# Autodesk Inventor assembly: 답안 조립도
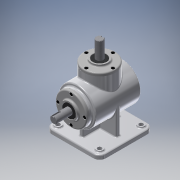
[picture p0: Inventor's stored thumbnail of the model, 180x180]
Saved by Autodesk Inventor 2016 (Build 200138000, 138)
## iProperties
Created: 2015-07
Part Number: 답안 조립도
Document SubType Name: Assembly
Designer: Administrator
Author: Administrator
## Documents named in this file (14)
- C:\Users\Administrator\Desktop\450706V1007\답안 조립도.iam
- C:\Users\Administrator\Desktop\450706V1007\본체.ipt
- C:\Users\Administrator\Desktop\450706V1007\커버.ipt
- C:\Users\Administrator\Desktop\450706V1007\메인 축.ipt
- 메인 축.ipt
- C:\Users\Administrator\Desktop\450706V1007\키 5x5.ipt
- C:\Users\Administrator\Desktop\450706V1007\메인 베벨기어.ipt
- C:\Users\Administrator\Desktop\450706V1007\베어링 6203.ipt
- C:\Users\Administrator\Desktop\450706V1007\서브 축.ipt
- 서브 축.ipt
- C:\Users\Administrator\Desktop\450706V1007\키 4x4.ipt
- C:\Users\Administrator\Desktop\450706V1007\서브 베벨기어.ipt
- C:\Users\Administrator\Desktop\450706V1007\오일실.ipt
- C:\Users\Administrator\Desktop\450706V1007\M4.ipt
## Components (8 placed, 1 different names)
1. M4:1
2. M4:2
3. M4:3
4. M4:4
5. M4:5
6. M4:6
7. M4:7
8. M4:8
